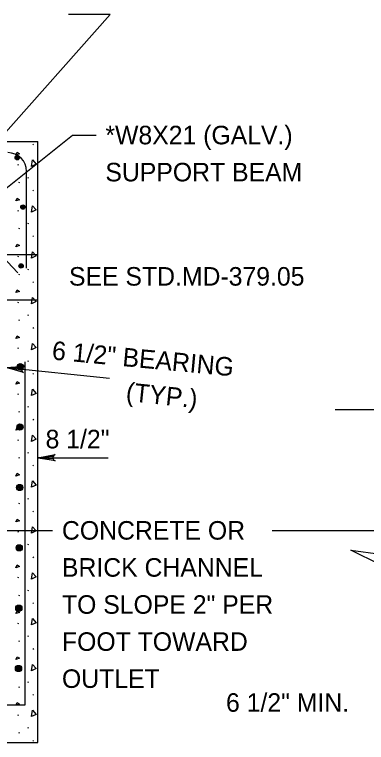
# Model space of a CAD drawing. Extents: x 2.4 to 9.7, y 1.1 to 11.2.
# Drawn here: x 4.657 to 5.797, y 8.562 to 10.918 of the extents above; entities that cross this region are included whole.
import ezdxf

# ---------------------------------------------------------------- set-up
doc = ezdxf.new("R2010")
doc.units = 0
for name, color, linetype in [('DETL-DIMS', 7, 'Continuous'), ('DETL-LINE', 7, 'Continuous'), ('DETL-NOTE', 7, 'Continuous'), ('DETL-PATT', 7, 'Continuous')]:
    doc.layers.add(name, color=color, linetype=linetype)

msp = doc.modelspace()

# ---------------------------------------------------------------- linework, layer by layer
at = {"layer": 'DETL-DIMS'}
for p, q in [((4.6016, 10.5079), (4.967, 10.9182)), ((4.967, 10.9182), (4.8315, 10.9182)), ((4.179, 9.9951), (4.8454, 10.5282)), ((4.8454, 10.5282), (4.9211, 10.5282)), ((4.6311, 9.7757), (4.9644, 9.7411)), ((5.6957, 9.6398), (6.0916, 9.6398)), ((4.7324, 9.4838), (4.9607, 9.4838)), ((4.2679, 9.2486), (4.7805, 9.2486)), ((5.491, 9.2486), (6.7976, 9.2486))]:
    msp.add_line(p, q, dxfattribs=at)
for points in [[(4.6311, 9.7757), (4.6884, 9.7804), (4.6838, 9.7779), (4.6811, 9.7743), (4.6801, 9.7706), (4.6804, 9.7668), (4.6822, 9.7628), (4.6862, 9.7594), (4.6311, 9.7757), (4.6822, 9.7628), (4.6804, 9.7668), (4.6311, 9.7757), (4.6801, 9.7706), (4.6811, 9.7743), (4.6311, 9.7757), (4.6838, 9.7779)], [(4.7324, 9.4838), (4.7889, 9.4944), (4.7846, 9.4914), (4.7823, 9.4876), (4.7817, 9.4838), (4.7823, 9.48), (4.7846, 9.4762), (4.7889, 9.4732), (4.7324, 9.4838), (4.7846, 9.4762), (4.7823, 9.48), (4.7324, 9.4838), (4.7817, 9.4838), (4.7823, 9.4876), (4.7324, 9.4838), (4.7846, 9.4914)], [(5.8425, 9.1372), (5.7458, 9.1845), (5.938, 9.1584), (5.8425, 9.2038)]]:
    msp.add_lwpolyline(points, dxfattribs=at)
at = {"layer": 'DETL-LINE'}
for p, q in [((4.3082, 10.5076), (4.7324, 10.5076)), ((4.7324, 8.5621), (4.7324, 10.5076)), ((4.6678, 10.0818), (4.3432, 10.4289)), ((4.6961, 10.0968), (4.6961, 10.4106)), ((4.49, 10.1416), (4.7324, 10.1416)), ((4.49, 9.9951), (4.7324, 9.9951)), ((4.6914, 8.6833), (4.6914, 9.7941)), ((4.531, 8.6833), (4.6914, 8.6833)), ((2.7749, 8.5621), (4.7324, 8.5621))]:
    msp.add_line(p, q, dxfattribs=at)
for centre, radius in [((4.6659, 10.4547), 0.00707), ((4.6659, 10.4547), 0.0053), ((4.6659, 10.4547), 0.00354), ((4.6659, 10.4547), 0.00177), ((4.6842, 10.295), 0.00707), ((4.6842, 10.295), 0.0053), ((4.6842, 10.295), 0.00354), ((4.6842, 10.295), 0.00177), ((4.6786, 10.1045), 0.00707), ((4.6786, 10.1045), 0.0053), ((4.6786, 10.1045), 0.00354), ((4.6786, 10.1045), 0.00177), ((4.676, 9.7781), 0.0101), ((4.676, 9.7781), 0.00758), ((4.676, 9.7781), 0.00505), ((4.676, 9.7781), 0.00253), ((4.6748, 9.5828), 0.0101), ((4.6748, 9.5828), 0.00758), ((4.6748, 9.5828), 0.00505), ((4.6748, 9.5828), 0.00253), ((4.6736, 9.3874), 0.0101), ((4.6736, 9.3874), 0.00758), ((4.6736, 9.3874), 0.00505), ((4.6736, 9.3874), 0.00253), ((4.6724, 9.1921), 0.0101), ((4.6724, 9.1921), 0.00758), ((4.6724, 9.1921), 0.00505), ((4.6724, 9.1921), 0.00253), ((4.6712, 8.9967), 0.0101), ((4.6712, 8.9967), 0.00758), ((4.6712, 8.9967), 0.00505), ((4.6712, 8.9967), 0.00253), ((4.67, 8.8014), 0.0101), ((4.67, 8.8014), 0.00758), ((4.67, 8.8014), 0.00505), ((4.67, 8.8014), 0.00253)]:
    msp.add_circle(centre, radius, dxfattribs=at)
msp.add_arc((4.6355, 10.4106), 0.0606, 0, 90, dxfattribs=at)
at = {"layer": 'DETL-PATT'}
for p, q in [((4.7167, 10.4986), (4.7183, 10.4962)), ((4.6688, 10.4306), (4.67, 10.4338)), ((4.701, 10.3891), (4.7026, 10.3923)), ((4.672, 10.3731), (4.6736, 10.3763)), ((4.7167, 10.3502), (4.7183, 10.3477)), ((4.6688, 10.2821), (4.67, 10.2853)), ((4.672, 10.2247), (4.6736, 10.2279)), ((4.701, 10.2407), (4.7026, 10.2439)), ((4.7167, 10.2017), (4.7183, 10.1993)), ((4.6688, 10.1337), (4.67, 10.1369)), ((4.701, 10.0922), (4.7026, 10.0954)), ((4.672, 10.0762), (4.6736, 10.0794)), ((4.7167, 10.0533), (4.7183, 10.0509)), ((4.6688, 9.9852), (4.67, 9.9885)), ((4.701, 9.9438), (4.7026, 9.947)), ((4.672, 9.9278), (4.6736, 9.931)), ((4.7167, 9.9048), (4.7183, 9.9024)), ((4.6688, 9.8368), (4.67, 9.84)), ((4.672, 9.7794), (4.6736, 9.7826)), ((4.701, 9.7953), (4.7026, 9.7986)), ((4.7167, 9.7564), (4.7183, 9.754)), ((4.6688, 9.6884), (4.67, 9.6916)), ((4.701, 9.6469), (4.7026, 9.6501)), ((4.672, 9.6309), (4.6736, 9.6341)), ((4.7167, 9.608), (4.7183, 9.6056)), ((4.6688, 9.5399), (4.67, 9.5432)), ((4.701, 9.4985), (4.7026, 9.5017)), ((4.672, 9.4825), (4.6736, 9.4857)), ((4.7167, 9.4595), (4.7183, 9.4571)), ((4.6688, 9.3915), (4.67, 9.3947)), ((4.672, 9.334), (4.6736, 9.3373)), ((4.701, 9.35), (4.7026, 9.3532)), ((4.7167, 9.3111), (4.7183, 9.3087)), ((4.6688, 9.2431), (4.67, 9.2463)), ((4.701, 9.2016), (4.7026, 9.2048)), ((4.672, 9.1856), (4.6736, 9.1888)), ((4.7167, 9.1627), (4.7183, 9.1602)), ((4.6688, 9.0946), (4.67, 9.0978)), ((4.701, 9.0532), (4.7026, 9.0564)), ((4.672, 9.0372), (4.6736, 9.0404)), ((4.7167, 9.0142), (4.7183, 9.0118)), ((4.6688, 8.9462), (4.67, 8.9494)), ((4.701, 8.9047), (4.7026, 8.9079)), ((4.672, 8.8887), (4.6736, 8.8919)), ((4.7167, 8.8658), (4.7183, 8.8634)), ((4.6688, 8.7977), (4.67, 8.801)), ((4.672, 8.7403), (4.6736, 8.7435)), ((4.701, 8.7563), (4.7026, 8.7595)), ((4.7167, 8.7173), (4.7183, 8.7149)), ((4.6688, 8.6493), (4.67, 8.6525)), ((4.701, 8.6078), (4.7026, 8.6111)), ((4.672, 8.5919), (4.6736, 8.5951)), ((4.7167, 8.5689), (4.7183, 8.5665))]:
    msp.add_line(p, q, dxfattribs=at)
for points in [[(4.6615, 10.4636), (4.666, 10.4724), (4.6728, 10.4672), (4.6615, 10.4636)], [(4.7123, 10.4269), (4.7151, 10.4475), (4.7276, 10.4342), (4.7123, 10.4269)], [(4.6615, 10.3151), (4.666, 10.324), (4.6728, 10.3188), (4.6615, 10.3151)], [(4.7123, 10.2785), (4.7151, 10.299), (4.7276, 10.2857), (4.7123, 10.2785)], [(4.6615, 10.1667), (4.666, 10.1755), (4.6728, 10.1703), (4.6615, 10.1667)], [(4.7123, 10.1301), (4.7151, 10.1506), (4.7276, 10.1373), (4.7123, 10.1301)], [(4.6615, 10.0183), (4.666, 10.0271), (4.6728, 10.0219), (4.6615, 10.0183)], [(4.7123, 9.9816), (4.7151, 10.0022), (4.7276, 9.9889), (4.7123, 9.9816)], [(4.6615, 9.8698), (4.666, 9.8787), (4.6728, 9.8734), (4.6615, 9.8698)], [(4.7123, 9.8332), (4.7151, 9.8537), (4.7276, 9.8404), (4.7123, 9.8332)], [(4.6615, 9.7214), (4.666, 9.7302), (4.6728, 9.725), (4.6615, 9.7214)], [(4.7123, 9.6847), (4.7151, 9.7053), (4.7276, 9.692), (4.7123, 9.6847)], [(4.6615, 9.5729), (4.666, 9.5818), (4.6728, 9.5766), (4.6615, 9.5729)], [(4.7123, 9.5363), (4.7151, 9.5568), (4.7276, 9.5436), (4.7123, 9.5363)], [(4.6615, 9.4245), (4.666, 9.4334), (4.6728, 9.4281), (4.6615, 9.4245)], [(4.7123, 9.3879), (4.7151, 9.4084), (4.7276, 9.3951), (4.7123, 9.3879)], [(4.6615, 9.2761), (4.666, 9.2849), (4.6728, 9.2797), (4.6615, 9.2761)], [(4.7123, 9.2394), (4.7151, 9.26), (4.7276, 9.2467), (4.7123, 9.2394)], [(4.6615, 9.1276), (4.666, 9.1365), (4.6728, 9.1313), (4.6615, 9.1276)], [(4.7123, 9.091), (4.7151, 9.1115), (4.7276, 9.0982), (4.7123, 9.091)], [(4.6615, 8.9792), (4.666, 8.988), (4.6728, 8.9828), (4.6615, 8.9792)], [(4.7123, 8.9426), (4.7151, 8.9631), (4.7276, 8.9498), (4.7123, 8.9426)], [(4.6615, 8.8308), (4.666, 8.8396), (4.6728, 8.8344), (4.6615, 8.8308)], [(4.7123, 8.7941), (4.7151, 8.8147), (4.7276, 8.8014), (4.7123, 8.7941)], [(4.6615, 8.6823), (4.666, 8.6912), (4.6728, 8.6859), (4.6615, 8.6823)], [(4.7123, 8.6457), (4.7151, 8.6662), (4.7276, 8.6529), (4.7123, 8.6457)]]:
    msp.add_lwpolyline(points, dxfattribs=at)

# ---------------------------------------------------------------- texts
at = {"layer": 'DETL-NOTE'}
for s, p in [('*W8X21 (GALV.)', (4.9514, 10.4982)), ('SUPPORT BEAM', (4.9514, 10.3782)), ('SEE STD.MD-379.05', (4.8336, 10.0408)), ('8 1/2"', (4.7578, 9.5141)), ('CONCRETE OR ', (4.8108, 9.2186)), ('BRICK CHANNEL', (4.8108, 9.0986)), ('TO SLOPE 2" PER', (4.8108, 8.9786)), ('FOOT TOWARD', (4.8108, 8.8586)), ('OUTLET', (4.8108, 8.7386)), ('6 1/2" MIN.', (5.342, 8.6614))]:
    msp.add_text(s, height=0.06, dxfattribs=at).set_placement(p)
for s, rotation, p in [('6 1/2" BEARING', 354.6823, (4.7767, 9.8018)), ('(TYP.)', 354.0649, (5.016, 9.6679))]:
    msp.add_text(s, height=0.06, rotation=rotation, dxfattribs=at).set_placement(p)

doc.saveas('drawing.dxf')
